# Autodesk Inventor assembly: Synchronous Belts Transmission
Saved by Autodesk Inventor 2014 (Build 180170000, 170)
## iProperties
Created: 2013-12
Part Number: Synchronous Belts Transmission
Document SubType Name: Assembly
Designer: Bram
ClientObjectVersion: 1
Author: Bram
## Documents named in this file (3)
- D:\gDrive\Google Drive\Hobby\3D Printer\3D printer\Inventor\PrinterAssambly\Design Accelerator\Synchronous Belts Transmission1.iam
- D:\gDrive\Google Drive\Hobby\3D Printer\3D printer\Inventor\PrinterAssambly\Design Accelerator\Synchronous Belt1.ipt
- D:\gDrive\Google Drive\Hobby\3D Printer\3D printer\Inventor\PrinterAssambly\Design Accelerator\Synchronous Pulley11.ipt
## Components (3 placed, 2 different names)
1. Synchronous Belt:1 — Flush:1, Flush:2
2. Synchronous Pulley1:1 — Flush:1, Rotation:1
3. Synchronous Pulley1:2 — Flush:2, Rotation:1
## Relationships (3: Flush 2, RelateRotation 1)
- Flush:1: Synchronous Belt:1 ↔ Synchronous Pulley1:1
- Flush:2: Synchronous Belt:1 ↔ Synchronous Pulley1:2
- Rotation:1 [RelateRotation]: Synchronous Pulley1:1 ↔ Synchronous Pulley1:2
